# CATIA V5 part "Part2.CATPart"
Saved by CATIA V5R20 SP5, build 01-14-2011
Part number: 凸缘压板
Bounding box of the stored display mesh (mm): x -39.452 to 40.548, y -20.432 to 45, z 0 to 40
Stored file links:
  E:\画图\Part2.CATPart
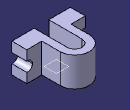
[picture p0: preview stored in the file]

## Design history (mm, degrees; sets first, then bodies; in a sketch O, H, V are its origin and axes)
Body1 (main body)
  Sketch1 on xy-plane, origin (0, 0, 0), H (1, 0, 0), V (0, 1, 0)
    line L1 (-39.4524, 0) -> (-20, 0)
    point P1 (-39.4524, 0)
    line L2 (-39.4524, 0) -> (-39.4524, -20.4322)
    point P3 (-39.4524, -20.4322)
    line L3 (-39.4524, -20.4322) -> (-10, -20.4322)
    point P4 (40.5476, -20.4322)
    line L4 (40.5476, 0) -> (40.5476, -20.4322)
    arc A1 centre (0, 25) radius 10 from (10, 25) to (-10, 25) ccw
    point P5 (0, 25)
    arc A2 centre (0, 25) radius 20 from (20, 25) to (-20, 25) ccw
    line L5 (-20, 25) -> (-20, 0)
    line L6 (20, 25) -> (20, 0)
    point P9 (20, 0)
    line L7 (-10, 25) -> (-10, -20.4322)
    line L8 (10, 25) -> (10, -20.4322)
    point P13 (10, -20.4322)
    line L9 (20, 0) -> (40.5476, 0)
    line L10 (10, -20.4322) -> (40.5476, -20.4322)
    radius A1 = 10
    radius A2 = 20
    distance P3 P4 = 80
    distance P5 O = 25
    coincidence: P1 H, P5 V, P9 L1, P13 L3, L1 L9, L3 L10
    horizontal: L1 H, L3 H, L9 H, L10 H
    vertical: L2 V, L4 V
    tangency: L5 A2, L6 A2, L7 A1, L8 A1
  Pad1: profile Sketch1, direction (0, 0, 1), length 40
  Sketch2 on face of Pad1 from Sketch1.L9, origin (0, 0, 0), H (-1, 0, 0), V (0, 0, 1)
    circle A1 centre (-39.3232, 19.8208) radius 6.6872
  Pocket1: profile Sketch2, direction (0, -1, 0), length 40
  Mirror1: of Pocket1, about yz-plane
